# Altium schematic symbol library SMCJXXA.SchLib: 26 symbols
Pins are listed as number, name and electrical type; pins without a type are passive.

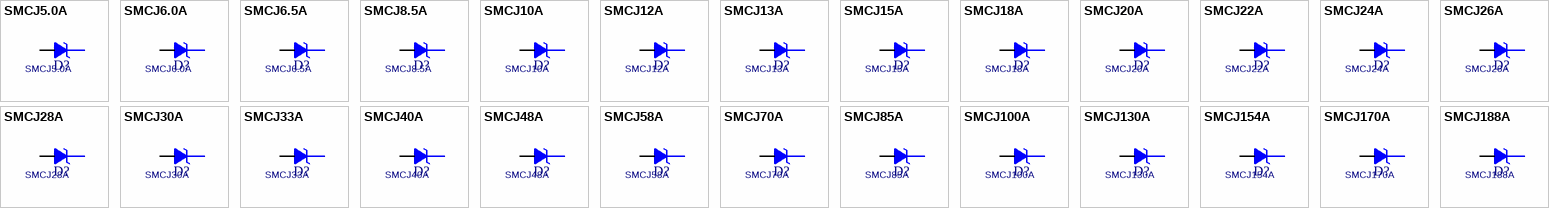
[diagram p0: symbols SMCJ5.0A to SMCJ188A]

## SMCJ5.0A
designator D?
footprint ST_SMC
pins: 1 K, 2 A

## SMCJ6.0A
designator D?
footprint ST_SMC
pins: 1 K, 2 A

## SMCJ6.5A
designator D?
footprint ST_SMC
pins: 1 K, 2 A

## SMCJ8.5A
designator D?
footprint ST_SMC
pins: 1 K, 2 A

## SMCJ10A
designator D?
footprint ST_SMC
pins: 1 K, 2 A

## SMCJ12A
designator D?
footprint ST_SMC
pins: 1 K, 2 A

## SMCJ13A
designator D?
footprint ST_SMC
pins: 1 K, 2 A

## SMCJ15A
designator D?
footprint ST_SMC
pins: 1 K, 2 A

## SMCJ18A
designator D?
footprint ST_SMC
pins: 1 K, 2 A

## SMCJ20A
designator D?
footprint ST_SMC
pins: 1 K, 2 A

## SMCJ22A
designator D?
footprint ST_SMC
pins: 1 K, 2 A

## SMCJ24A
designator D?
footprint ST_SMC
pins: 1 K, 2 A

## SMCJ26A
designator D?
footprint ST_SMC
pins: 1 K, 2 A

## SMCJ28A
designator D?
footprint ST_SMC
pins: 1 K, 2 A

## SMCJ30A
designator D?
footprint ST_SMC
pins: 1 K, 2 A

## SMCJ33A
designator D?
footprint ST_SMC
pins: 1 K, 2 A

## SMCJ40A
designator D?
footprint ST_SMC
pins: 1 K, 2 A

## SMCJ48A
designator D?
footprint ST_SMC
pins: 1 K, 2 A

## SMCJ58A
designator D?
footprint ST_SMC
pins: 1 K, 2 A

## SMCJ70A
designator D?
footprint ST_SMC
pins: 1 K, 2 A

## SMCJ85A
designator D?
footprint ST_SMC
pins: 1 K, 2 A

## SMCJ100A
designator D?
footprint ST_SMC
pins: 1 K, 2 A

## SMCJ130A
designator D?
footprint ST_SMC
pins: 1 K, 2 A

## SMCJ154A
designator D?
footprint ST_SMC
pins: 1 K, 2 A

## SMCJ170A
designator D?
footprint ST_SMC
pins: 1 K, 2 A

## SMCJ188A
designator D?
footprint ST_SMC
pins: 1 K, 2 A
